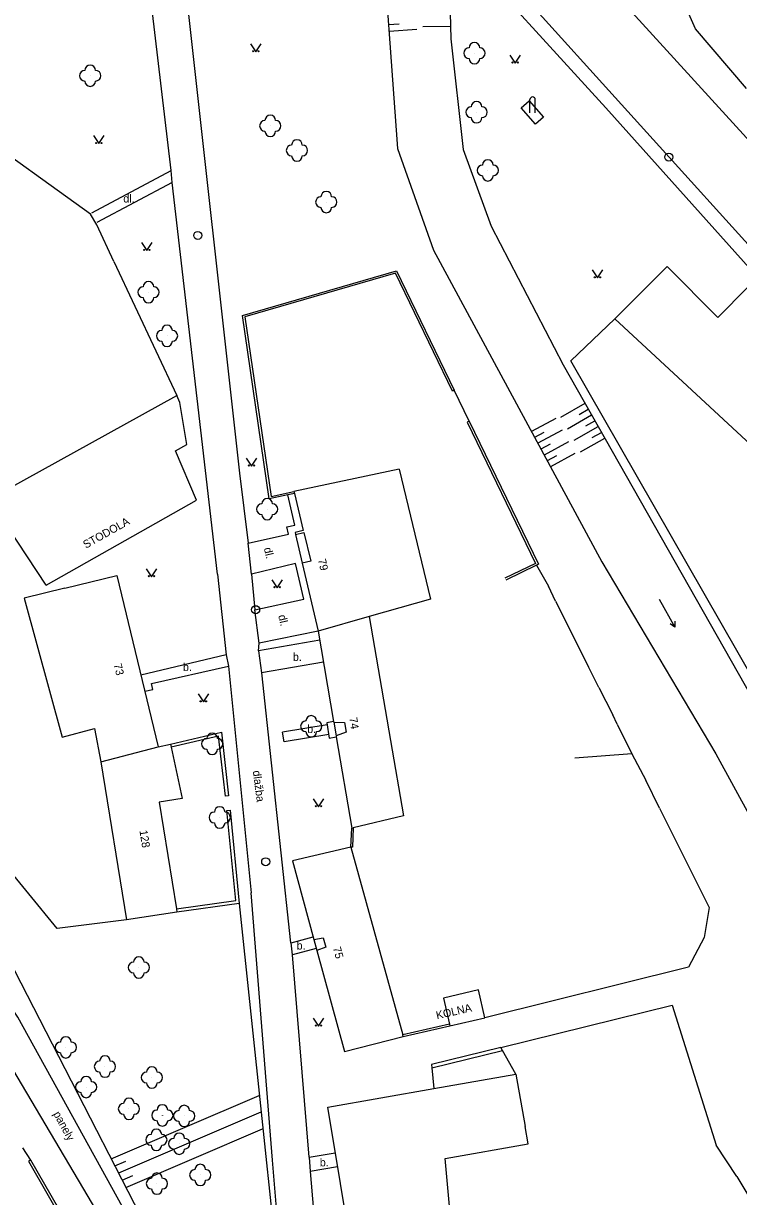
# Model space of a CAD drawing. Extents: x -582162 to -561283, y -1187583 to -1183539.
# Drawn here: x -569806.3 to -569739.3, y -1185483.7 to -1185373.8 of the extents above; entities that cross this region are included whole.
import ezdxf

# ---------------------------------------------------------------- set-up
doc = ezdxf.new("R2010")
doc.units = 0
for name, color, linetype in [('Vrstva 1', 7, 'Continuous'), ('Vrstva 10', 7, 'Continuous'), ('Vrstva 11', 7, 'Continuous'), ('Vrstva 12', 7, 'Continuous'), ('Vrstva 14', 7, 'Continuous'), ('Vrstva 3', 7, 'Continuous'), ('Vrstva 4', 7, 'Continuous'), ('Vrstva 5', 7, 'Continuous'), ('Vrstva 6', 7, 'Continuous'), ('Vrstva 9', 7, 'Continuous')]:
    doc.layers.add(name, color=color, linetype=linetype)

# ---------------------------------------------------------------- blocks, each defined once
blk = doc.blocks.new('1.079')
at = {"layer": 'Vrstva 1'}
for radius in [0.75, 0.001]:
    blk.add_circle((0, -0.001), radius, dxfattribs=at)
blk = doc.blocks.new('3.130')
at = {"layer": 'Vrstva 1'}
blk.add_circle((0, 0), 0.001, dxfattribs=at)
for centre, start, end in [((-1, 0), 90, 270), ((0, 1), 0, 180), ((1, 0), 270, 90), ((0, -1), 180, 360)]:
    blk.add_arc(centre, 1, start, end, dxfattribs=at)
blk = doc.blocks.new('3.140')
at = {"layer": 'Vrstva 1'}
blk.add_lwpolyline([(-1, 1.5), (0, 0), (1, 1.5)], dxfattribs=at)
for centre in [(-0.5, 0.1), (0.5, 0.1)]:
    blk.add_circle(centre, 0.1, dxfattribs=at)
blk = doc.blocks.new('8.021')
at = {"layer": 'Vrstva 1'}
blk.add_line((-3, 0), (3, 0), dxfattribs=at)
blk.add_lwpolyline([(2, 0.5), (3, 0), (2, -0.5)], dxfattribs=at)
blk = doc.blocks.new('4.140')
at = {"layer": 'Vrstva 1'}
for p, q in [((-0.5, 0), (-0.5, 2.5)), ((0.5, 0), (0.5, 2.5))]:
    blk.add_line(p, q, dxfattribs=at)
blk.add_arc((0, 2.5), 0.5, 0, 180, dxfattribs=at)

msp = doc.modelspace()

# ---------------------------------------------------------------- linework, layer by layer
at = {"layer": 'Vrstva 10'}
for points in [[(-569792.52, -1185387.59), (-569796.74, -1185351.64)], [(-569766.7, -1185353.66), (-569755.51, -1185365.95), (-569731.77, -1185392.03)], [(-569766.54, -1185365.49), (-569751.79, -1185381.72), (-569737.53, -1185397.61), (-569728.89, -1185405.93), (-569729.86, -1185407.01)], [(-569791.22, -1185369.85), (-569786.11, -1185415.95)], [(-569760.68, -1185369.9), (-569736.38, -1185396.8)], [(-569758.96, -1185381.06), (-569757.62, -1185382.58), (-569758.37, -1185383.24), (-569759.71, -1185381.72), (-569758.96, -1185381.06)], [(-569799.94, -1185391.56), (-569792.52, -1185387.59)], [(-569792.41, -1185388.69), (-569792.52, -1185387.59)], [(-569792.41, -1185388.69), (-569799.48, -1185392.45)], [(-569788.16, -1185425.41), (-569792.41, -1185388.69)], [(-569786.11, -1185415.95), (-569785.29, -1185422.52)], [(-569778.74, -1185430.74), (-569784.26, -1185431.87), (-569784.66, -1185428.77), (-569780.07, -1185427.76), (-569780.86, -1185424.4), (-569784.97, -1185425.41), (-569785.29, -1185422.52), (-569781.51, -1185421.65), (-569781.66, -1185420.98), (-569780.91, -1185420.81), (-569781.57, -1185417.98)], [(-569788.16, -1185425.41), (-569787.36, -1185432.97)], [(-569784.97, -1185425.41), (-569784.66, -1185428.77)], [(-569778.59, -1185431.61), (-569784.32, -1185432.59)], [(-569784.32, -1185432.59), (-569784.26, -1185431.87)], [(-569787.36, -1185432.97), (-569795.34, -1185434.89)], [(-569787.36, -1185432.97), (-569787.12, -1185434.03), (-569785.01, -1185455.27)], [(-569784.32, -1185432.59), (-569784.05, -1185434.65), (-569781.32, -1185459.97)], [(-569794.22, -1185436.21), (-569794.35, -1185435.66), (-569787.12, -1185434.03)], [(-569778.24, -1185433.66), (-569784.05, -1185434.65)], [(-569794.97, -1185436.39), (-569794.22, -1185436.21)], [(-569777.9, -1185439.53), (-569782.06, -1185440.22)], [(-569777.29, -1185439.23), (-569777.93, -1185439.33), (-569777.69, -1185440.78), (-569777.04, -1185440.67)], [(-569777.74, -1185440.45), (-569781.92, -1185441.14), (-569782.06, -1185440.22)], [(-569780.8, -1185506.94), (-569781.54, -1185507.5), (-569792.42, -1185493.14), (-569806.86, -1185466.92), (-569817.24, -1185451.15)], [(-569780.8, -1185506.94), (-569783.01, -1185480.34), (-569785.01, -1185455.27)], [(-569781.25, -1185459.96), (-569779.21, -1185459.4)], [(-569781.13, -1185461.08), (-569781.25, -1185459.96)], [(-569778.91, -1185460.48), (-569781.13, -1185461.08)], [(-569779.59, -1185480.04), (-569781.13, -1185461.08)], [(-569809.61, -1185468.04), (-569794.15, -1185494.14), (-569783.11, -1185508.79), (-569780.17, -1185513.91)], [(-569768.09, -1185471.68), (-569767.88, -1185473.61)], [(-569779.59, -1185480.04), (-569777.13, -1185479.65)], [(-569779.59, -1185480.04), (-569779.49, -1185481.38)], [(-569776.91, -1185480.96), (-569779.49, -1185481.38)], [(-569779.49, -1185481.38), (-569776.65, -1185514.67), (-569774.41, -1185542.31)]]:
    msp.add_lwpolyline(points, dxfattribs=at)
at = {"layer": 'Vrstva 12'}
for points in [[(-569771.15, -1185373.86), (-569772.14, -1185373.93)], [(-569768.93, -1185374.1), (-569766.32, -1185374.04)], [(-569769.5, -1185374.37), (-569772.09, -1185374.56)], [(-569755.99, -1185410.69), (-569753.73, -1185409.4)], [(-569754.28, -1185410.44), (-569753.42, -1185409.95)], [(-569756.46, -1185410.81), (-569758.75, -1185412.05)], [(-569755.37, -1185411.78), (-569753.11, -1185410.49)], [(-569753.66, -1185411.52), (-569752.8, -1185411.03)], [(-569757.58, -1185412.12), (-569758.45, -1185412.6)], [(-569755.86, -1185411.91), (-569758.16, -1185413.15)], [(-569754.76, -1185412.86), (-569752.49, -1185411.58)], [(-569753.05, -1185412.61), (-569752.18, -1185412.12)], [(-569756.98, -1185413.22), (-569757.86, -1185413.7)], [(-569755.27, -1185413.01), (-569757.56, -1185414.25)], [(-569754.14, -1185413.95), (-569751.87, -1185412.66)], [(-569756.39, -1185414.32), (-569757.27, -1185414.8)], [(-569754.68, -1185414.11), (-569756.97, -1185415.35)], [(-569786.12, -1185456.27), (-569780.8, -1185506.94)], [(-569807.78, -1185461.41), (-569790.07, -1185495.9)], [(-569798.13, -1185480.2), (-569784.27, -1185474.26)], [(-569784.11, -1185475.84), (-569797.44, -1185481.54)], [(-569796.76, -1185482.88), (-569783.95, -1185477.4)], [(-569797.79, -1185480.87), (-569796.76, -1185480.43)], [(-569797.1, -1185482.21), (-569796.1, -1185481.78)]]:
    msp.add_lwpolyline(points, dxfattribs=at)
at = {"layer": 'Vrstva 4'}
for points in [[(-569750.93, -1185401.47), (-569746.04, -1185396.59), (-569741.28, -1185401.36), (-569738.47, -1185398.51), (-569729.86, -1185407.01)], [(-569804.23, -1185426.44), (-569790.12, -1185418.49), (-569792.1, -1185413.84), (-569791.05, -1185413.25), (-569791.68, -1185409.32), (-569791.96, -1185408.67)], [(-569771.15, -1185415.56), (-569781, -1185417.66)], [(-569781, -1185417.66), (-569780.95, -1185417.85)], [(-569780.95, -1185417.85), (-569780.13, -1185421.33), (-569780.9, -1185421.51), (-569780.86, -1185421.69)], [(-569780.86, -1185421.69), (-569780.06, -1185421.5), (-569779.43, -1185424.2), (-569780.23, -1185424.39)], [(-569780.86, -1185421.69), (-569780.23, -1185424.39)], [(-569780.23, -1185424.39), (-569778.74, -1185430.74)], [(-569802.47, -1185426.72), (-569797.61, -1185425.54), (-569793.71, -1185441.58)], [(-569778.74, -1185430.74), (-569777.29, -1185439.23)], [(-569777.29, -1185439.23), (-569777.28, -1185439.29)], [(-569777.28, -1185439.29), (-569777.06, -1185440.57)], [(-569777.28, -1185439.29), (-569776.26, -1185439.32), (-569776.11, -1185440.21), (-569777.06, -1185440.57)], [(-569777.06, -1185440.57), (-569777.04, -1185440.67)], [(-569777.04, -1185440.67), (-569775.59, -1185449.21)], [(-569793.71, -1185441.58), (-569792.56, -1185441.33)], [(-569792.5, -1185441.62), (-569791.49, -1185446.44), (-569793.63, -1185446.78), (-569792.01, -1185456.79)], [(-569792.56, -1185441.33), (-569792.5, -1185441.62)], [(-569775.59, -1185449.21), (-569775.44, -1185449.18)], [(-569775.67, -1185450.99), (-569781.15, -1185452.29), (-569779.14, -1185459.64)], [(-569791.96, -1185457.09), (-569796.69, -1185457.8)], [(-569792.01, -1185456.79), (-569791.96, -1185457.09)], [(-569779.14, -1185459.64), (-569778.25, -1185459.5), (-569778.01, -1185460.36), (-569778.85, -1185460.69)], [(-569779.14, -1185459.64), (-569778.85, -1185460.69)], [(-569778.85, -1185460.69), (-569776.26, -1185470.15), (-569770.77, -1185468.74)], [(-569767, -1185465.14), (-569766.44, -1185467.6)], [(-569763.12, -1185467), (-569763.72, -1185464.38)], [(-569766.44, -1185467.6), (-569766.41, -1185467.75)], [(-569766.41, -1185467.75), (-569763.12, -1185467)], [(-569770.77, -1185468.74), (-569770.81, -1185468.59)], [(-569767.88, -1185473.61), (-569760.22, -1185472.26)], [(-569760.22, -1185472.26), (-569759.35, -1185477.18)], [(-569774.27, -1185496.84), (-569777.84, -1185475.37), (-569767.88, -1185473.61)]]:
    msp.add_lwpolyline(points, dxfattribs=at)
at = {"layer": 'Vrstva 5'}
for points in [[(-569750.93, -1185401.47), (-569728.04, -1185422.68)], [(-569804.23, -1185426.44), (-569809.55, -1185418.38), (-569791.96, -1185408.67)], [(-569771.15, -1185415.56), (-569768.21, -1185427.75), (-569773.95, -1185429.38), (-569778.74, -1185430.74)], [(-569802.47, -1185426.72), (-569806.29, -1185427.65), (-569802.73, -1185440.7), (-569799.7, -1185439.87), (-569799.1, -1185442.99), (-569793.71, -1185441.58)], [(-569773.95, -1185429.38), (-569771.95, -1185441.01), (-569770.74, -1185448.05), (-569775.44, -1185449.18)], [(-569799.1, -1185442.99), (-569796.69, -1185457.8)], [(-569775.67, -1185450.99), (-569770.81, -1185468.59)], [(-569763.72, -1185464.38), (-569767, -1185465.14)], [(-569773.53, -1185501.31), (-569756.73, -1185498.53), (-569757.69, -1185493.74), (-569765.5, -1185494.92), (-569766.83, -1185480.18), (-569759.06, -1185478.81), (-569759.35, -1185477.18)]]:
    msp.add_lwpolyline(points, dxfattribs=at)
at = {"layer": 'Vrstva 9'}
for points in [[(-569773.38, -1185357.76), (-569772.96, -1185362.74), (-569771.29, -1185385.53), (-569767.93, -1185395.06), (-569752.15, -1185424.26), (-569741.47, -1185442.25), (-569734.66, -1185454.71)], [(-569738.59, -1185379.9), (-569743.37, -1185374.29), (-569744.64, -1185371.45), (-569727.67, -1185359.71), (-569726.87, -1185360.54)], [(-569766.54, -1185365.49), (-569766.29, -1185375.23), (-569765.15, -1185385.61), (-569762.51, -1185392.81), (-569755.77, -1185405.8), (-569736.09, -1185440.46), (-569729.37, -1185451.66)], [(-569800.06, -1185391.66), (-569811.38, -1185383.54), (-569819.72, -1185390.33), (-569819.17, -1185391.38)], [(-569799.48, -1185392.67), (-569800.06, -1185391.66)], [(-569797.87, -1185396.1), (-569799.48, -1185392.67)], [(-569797.87, -1185396.1), (-569791.96, -1185408.67)], [(-569781.57, -1185417.98), (-569783.31, -1185418.36), (-569785.82, -1185401.16), (-569771.38, -1185396.97), (-569765.98, -1185408.16)], [(-569765.98, -1185408.16), (-569766.16, -1185408.25), (-569771.49, -1185397.21), (-569785.6, -1185401.3), (-569783.14, -1185418.12), (-569781, -1185417.66)], [(-569728.04, -1185422.68), (-569722.77, -1185428.17), (-569734.73, -1185440.91), (-569755.05, -1185405.43), (-569750.93, -1185401.47)], [(-569764.59, -1185411.08), (-569765.98, -1185408.16)], [(-569764.59, -1185411.08), (-569764.77, -1185411.17), (-569758.36, -1185424.4), (-569761.25, -1185425.8)], [(-569764.59, -1185411.08), (-569758.09, -1185424.49), (-569758.27, -1185424.58)], [(-569780.95, -1185417.85), (-569781.57, -1185417.98)], [(-569758.27, -1185424.58), (-569761.16, -1185425.98)], [(-569758.27, -1185424.58), (-569757.15, -1185426.54)], [(-569756.51, -1185427.94), (-569757.15, -1185426.54)], [(-569756.51, -1185427.94), (-569753.41, -1185434.09)], [(-569752.44, -1185436.03), (-569753.41, -1185434.09)], [(-569752.44, -1185436.03), (-569751.13, -1185438.61)], [(-569750.72, -1185439.48), (-569751.13, -1185438.61)], [(-569750.72, -1185439.48), (-569749.34, -1185442.25)], [(-569792.56, -1185441.33), (-569787.8, -1185440.21), (-569787.12, -1185446.19), (-569787.42, -1185446.22), (-569788.06, -1185440.58), (-569792.5, -1185441.62)], [(-569749.34, -1185442.25), (-569754.69, -1185442.65)], [(-569749.34, -1185442.25), (-569748.03, -1185444.73)], [(-569746.76, -1185447.35), (-569748.03, -1185444.73)], [(-569792.01, -1185456.79), (-569786.45, -1185456.01), (-569787.28, -1185447.56), (-569786.98, -1185447.53), (-569786.12, -1185456.27), (-569791.96, -1185457.09)], [(-569746.76, -1185447.35), (-569742.1, -1185456.64), (-569742.57, -1185459.47), (-569744.03, -1185462.25), (-569763.12, -1185467)], [(-569796.69, -1185457.8), (-569803.2, -1185458.62), (-569811.19, -1185448.87)], [(-569775.44, -1185449.18), (-569775.52, -1185451), (-569775.67, -1185450.99)], [(-569775.67, -1185450.99), (-569775.59, -1185449.21)], [(-569761.61, -1185469.78), (-569745.57, -1185465.82), (-569741.43, -1185478.93)], [(-569766.44, -1185467.6), (-569770.81, -1185468.59)], [(-569770.77, -1185468.74), (-569766.41, -1185467.75)], [(-569761.61, -1185469.78), (-569768.12, -1185471.38), (-569768.09, -1185471.68)], [(-569761.46, -1185470.05), (-569761.61, -1185469.78)], [(-569768.09, -1185471.68), (-569761.46, -1185470.05)], [(-569760.22, -1185472.26), (-569761.46, -1185470.05)], [(-569805.65, -1185480.32), (-569806.4, -1185479.16)], [(-569739.5, -1185481.87), (-569741.43, -1185478.93)], [(-569805.65, -1185480.32), (-569805.86, -1185480.44), (-569802.05, -1185487.09), (-569803.86, -1185488.13), (-569803.74, -1185488.34)], [(-569803.74, -1185488.34), (-569801.72, -1185487.18), (-569805.65, -1185480.32)], [(-569739.5, -1185481.87), (-569737.82, -1185484.68), (-569736.01, -1185490.69), (-569737.74, -1185508.78), (-569739.97, -1185532.95), (-569773.32, -1185533.72), (-569775.21, -1185515.35), (-569776.78, -1185498.35)]]:
    msp.add_lwpolyline(points, dxfattribs=at)

# ---------------------------------------------------------------- block references
at = {"layer": 'Vrstva 1', "xscale": 0.5, "yscale": 0.5}
for p in [(-569745.88, -1185386.32), (-569790.01, -1185393.66), (-569784.59, -1185428.74), (-569783.65, -1185452.36)]:
    msp.add_blockref('1.079', p, dxfattribs=at)
at = {"layer": 'Vrstva 11', "xscale": 0.5, "yscale": 0.5}
for p in [(-569764.09, -1185376.58), (-569800.09, -1185378.7), (-569763.89, -1185382.12), (-569783.22, -1185383.39), (-569780.72, -1185385.7), (-569762.84, -1185387.57), (-569777.97, -1185390.54), (-569794.63, -1185398.99), (-569792.89, -1185403.08), (-569783.51, -1185419.32), (-569779.38, -1185439.67), (-569788.66, -1185441.32), (-569787.96, -1185448.21), (-569795.53, -1185462.28), (-569802.37, -1185469.76), (-569798.71, -1185471.56), (-569794.31, -1185472.58), (-569800.47, -1185473.48), (-569796.46, -1185475.52), (-569793.33, -1185476.13), (-569791.28, -1185476.19), (-569793.89, -1185478.43), (-569791.75, -1185478.79), (-569789.78, -1185481.72), (-569793.84, -1185482.53)]:
    msp.add_blockref('3.130', p, dxfattribs=at)
at = {"layer": 'Vrstva 3', "xscale": 0.5, "yscale": 0.5}
for p in [(-569784.58, -1185376.45), (-569760.27, -1185377.51), (-569799.29, -1185385.06), (-569794.79, -1185395.07), (-569752.57, -1185397.64), (-569784.98, -1185415.28), (-569794.35, -1185425.65), (-569782.57, -1185426.68), (-569789.49, -1185437.38), (-569778.7, -1185447.21), (-569778.7, -1185467.77)]:
    msp.add_blockref('3.140', p, dxfattribs=at)
at = {"layer": 'Vrstva 3', "xscale": 0.49999999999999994, "yscale": 0.5, "rotation": -60.4119140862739}
msp.add_blockref('8.021', (-569746.04, -1185429.06), dxfattribs=at)
at = {"layer": 'Vrstva 9', "xscale": 0.5, "yscale": 0.5}
msp.add_blockref('4.140', (-569758.64, -1185382.19), dxfattribs=at)

# ---------------------------------------------------------------- texts
at = {"layer": 'Vrstva 14'}
for s, p in [('dl.', (-569796.99, -1185390.58)), ('b.', (-569781.1, -1185433.54)), ('b.', (-569791.4, -1185434.49)), ('b.', (-569779.76, -1185440.29)), ('b.', (-569780.75, -1185460.59)), ('b.', (-569778.58, -1185480.91))]:
    msp.add_text(s, height=0.75, dxfattribs=at).set_placement(p)
for s, rotation, p in [('STODOLA', 29.413, (-569800.5, -1185423.04)), ('dl.', 283.171, (-569783.83, -1185422.99)), ('dl.', 283.171, (-569782.48, -1185429.3)), ('dlažba', 277.378, (-569784.86, -1185443.86)), (' KOLNA', 12.842, (-569767.87, -1185467.2)), ('panely', 298.481, (-569803.57, -1185475.99))]:
    msp.add_text(s, height=0.75, rotation=rotation, dxfattribs=at).set_placement(p)
at = {"layer": 'Vrstva 6'}
for s, rotation, p in [('79', 283.171, (-569778.76, -1185424.06)), ('73', 283.666, (-569797.9, -1185433.88)), ('74', 279.678, (-569775.83, -1185438.89)), ('128', 279.201, (-569795.48, -1185449.45)), ('75', 285.312, (-569777.36, -1185460.44))]:
    msp.add_text(s, height=0.75, rotation=rotation, dxfattribs=at).set_placement(p)

doc.saveas('drawing.dxf')
